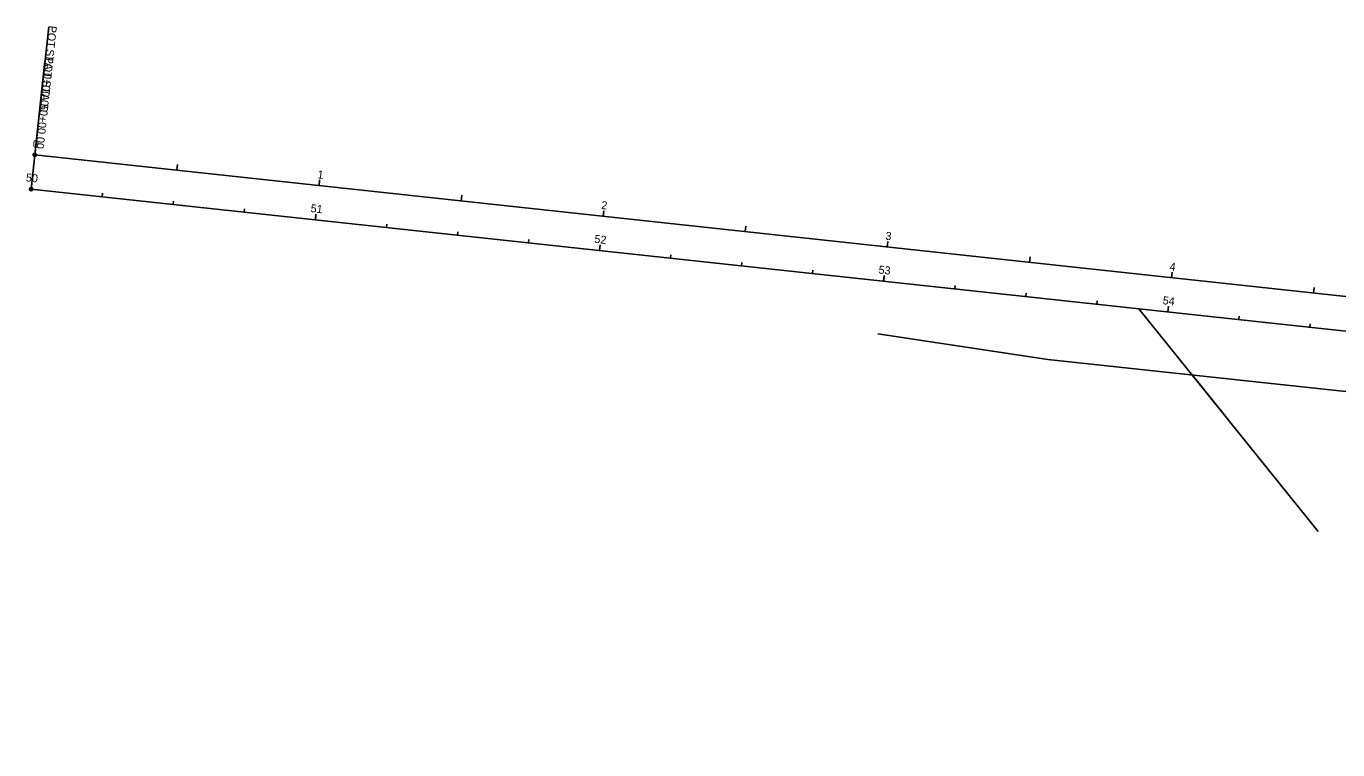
# Model space of a CAD drawing. Extents: x 1363416 to 1365241, y 422393 to 423801.
# Drawn here: x 1363415.8 to 1363874.7, y 423007.5 to 423260.5 of the extents above; entities that cross this region are included whole.
import ezdxf

# ---------------------------------------------------------------- set-up
doc = ezdxf.new("R2010")
doc.units = 0
for name, color, linetype in [('_CIVIL_CONSTRUCTION', 7, 'Continuous'), ('Default', 7, 'Continuous'), ('DT_X_Break_Line', 7, 'Continuous'), ('DT_X_Contour_Major', 7, 'Continuous'), ('DT_X_Island', 7, 'Continuous'), ('DT_X_Triangles', 7, 'Continuous'), ('MD_P_CURB_FACE_TOP', 7, 'Continuous'), ('MD_P_SAWCUT', 7, 'Continuous')]:
    doc.layers.add(name, color=color, linetype=linetype)

msp = doc.modelspace()

# ---------------------------------------------------------------- linework, layer by layer
at = {"layer": '_CIVIL_CONSTRUCTION'}
msp.add_line((1363417.51, 423203.55), (1365232.02, 423007.54), dxfattribs=at)
at = {"layer": 'Default'}
msp.add_line((1363823.71, 423138.55), (1363835.23, 423124.23), dxfattribs=at)
at = {"layer": 'DT_X_Break_Line'}
for p, q in [((1363418.8, 423215.48), (1363423.63, 423260.22)), ((1363418.8, 423215.48), (1363419.01, 423217.47)), ((1363418.8, 423215.48), (1365233.31, 423019.47)), ((1363418.8, 423215.48), (1364184.64, 423132.75)), ((1363418.8, 423215.48), (1364184.64, 423132.75)), ((1363468.51, 423210.11), (1363468.72, 423212.1)), ((1363518.22, 423204.74), (1363518.43, 423206.73)), ((1363567.93, 423199.37), (1363568.14, 423201.36)), ((1363617.64, 423194), (1363617.86, 423195.99)), ((1363667.35, 423188.63), (1363667.57, 423190.62)), ((1363717.06, 423183.26), (1363717.28, 423185.25)), ((1363766.77, 423177.89), (1363766.99, 423179.88)), ((1363816.48, 423172.52), (1363816.7, 423174.51)), ((1363866.19, 423167.15), (1363866.41, 423169.14)), ((1363713.79, 423152.94), (1363773.17, 423144.01)), ((1363713.79, 423152.94), (1363773.17, 423144.01)), ((1363713.79, 423152.94), (1363773.17, 423144.01)), ((1363713.79, 423152.94), (1363773.17, 423144.01)), ((1363773.17, 423144.01), (1364700.72, 423043.81)), ((1363773.17, 423144.01), (1364700.72, 423043.81)), ((1363773.17, 423144.01), (1364700.72, 423043.81)), ((1363773.17, 423144.01), (1364180.46, 423100.01))]:
    msp.add_line(p, q, dxfattribs=at)
msp.add_circle((1363418.8, 423215.48), 0.6, dxfattribs=at)
at = {"layer": 'DT_X_Contour_Major'}
for p, q in [((1363417.51, 423203.55), (1363417.72, 423205.54)), ((1363442.36, 423200.86), (1363442.49, 423202.06)), ((1363467.22, 423198.18), (1363467.35, 423199.37)), ((1363492.07, 423195.49), (1363492.2, 423196.69)), ((1363516.93, 423192.81), (1363517.15, 423194.8)), ((1363541.79, 423190.12), (1363541.91, 423191.32)), ((1363566.64, 423187.44), (1363566.77, 423188.63)), ((1363591.5, 423184.75), (1363591.63, 423185.95)), ((1363616.35, 423182.07), (1363616.57, 423184.06)), ((1363641.21, 423179.38), (1363641.34, 423180.58)), ((1363666.06, 423176.7), (1363666.19, 423177.89)), ((1363690.92, 423174.01), (1363691.05, 423175.21)), ((1363715.77, 423171.33), (1363715.99, 423173.32)), ((1363740.63, 423168.64), (1363740.76, 423169.84)), ((1363765.48, 423165.96), (1363765.61, 423167.15)), ((1363790.34, 423163.27), (1363790.47, 423164.47)), ((1363815.19, 423160.59), (1363815.41, 423162.58)), ((1363840.05, 423157.9), (1363840.18, 423159.1)), ((1363864.91, 423155.22), (1363865.03, 423156.41))]:
    msp.add_line(p, q, dxfattribs=at)
at = {"layer": 'DT_X_Island'}
msp.add_line((1363805.08, 423161.68), (1363867.79, 423083.78), dxfattribs=at)
at = {"layer": 'DT_X_Triangles'}
msp.add_line((1363417.51, 423203.55), (1363422.34, 423248.29), dxfattribs=at)
msp.add_circle((1363417.51, 423203.55), 0.6, dxfattribs=at)
at = {"layer": 'MD_P_CURB_FACE_TOP'}
msp.add_line((1363417.51, 423203.55), (1363422.34, 423248.29), dxfattribs=at)
msp.add_circle((1363417.51, 423203.55), 0.6, dxfattribs=at)
at = {"layer": 'MD_P_SAWCUT'}
for p, q in [((1363417.51, 423203.55), (1363417.72, 423205.54)), ((1363516.93, 423192.81), (1363517.06, 423194)), ((1363616.35, 423182.07), (1363616.48, 423183.26)), ((1363715.77, 423171.33), (1363715.9, 423172.52)), ((1363815.19, 423160.59), (1363815.32, 423161.78))]:
    msp.add_line(p, q, dxfattribs=at)

# ---------------------------------------------------------------- texts
at = {"layer": 'DT_X_Break_Line'}
for s, rotation, p in [('POT', 263.8345, (1363423.73, 423260.78)), (' STA. ', 263.8345, (1363422.96, 423253.62)), ('0+00.00', 263.8345, (1363421.94, 423244.22)), ('0', 353.8345, (1363417.96, 423218.08)), ('1', 353.8345, (1363517.58, 423207.32)), ('2', 353.8345, (1363616.87, 423196.6)), ('3', 353.8345, (1363716.3, 423185.86)), ('4', 353.8345, (1363815.72, 423175.12))]:
    msp.add_text(s, height=2.8, rotation=rotation, dxfattribs=at).set_placement(p)
at = {"layer": 'DT_X_Contour_Major'}
for s, p in [('50', (1363415.56, 423206.27)), ('51', (1363515.18, 423195.51)), ('52', (1363614.47, 423184.79)), ('53', (1363713.9, 423174.05)), ('54', (1363813.32, 423163.31))]:
    msp.add_text(s, height=2.8, rotation=353.8345, dxfattribs=at).set_placement(p)
at = {"layer": 'DT_X_Triangles'}
for s, p in [('POT', (1363422.56, 423249.96)), (' STA. ', (1363421.79, 423242.8)), ('50+00.00', (1363420.78, 423233.4))]:
    msp.add_text(s, height=2.8, rotation=263.8345, dxfattribs=at).set_placement(p)
at = {"layer": 'MD_P_CURB_FACE_TOP'}
for s, p in [('POT', (1363422.56, 423249.96)), (' STA. ', (1363421.79, 423242.8)), ('50+00.00', (1363420.78, 423233.4))]:
    msp.add_text(s, height=2.8, rotation=263.8345, dxfattribs=at).set_placement(p)
at = {"layer": 'MD_P_SAWCUT'}
msp.add_text('50', height=2.8, rotation=353.8345, dxfattribs=at).set_placement((1363415.56, 423206.27))

doc.saveas('drawing.dxf')
